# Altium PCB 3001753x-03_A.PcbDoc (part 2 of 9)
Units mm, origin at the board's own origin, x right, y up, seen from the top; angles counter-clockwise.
Board outline 210 x 130 mm, 8 copper layers (1-TOP, 2-GND, 3-INTOP, 4-PWR, 5-PWR, 6-INBOT, 7-GND, 8-BOTTOM), stack 1.646 mm thick; 676 components, 623 nets, 2861 pads, 2382 vias.
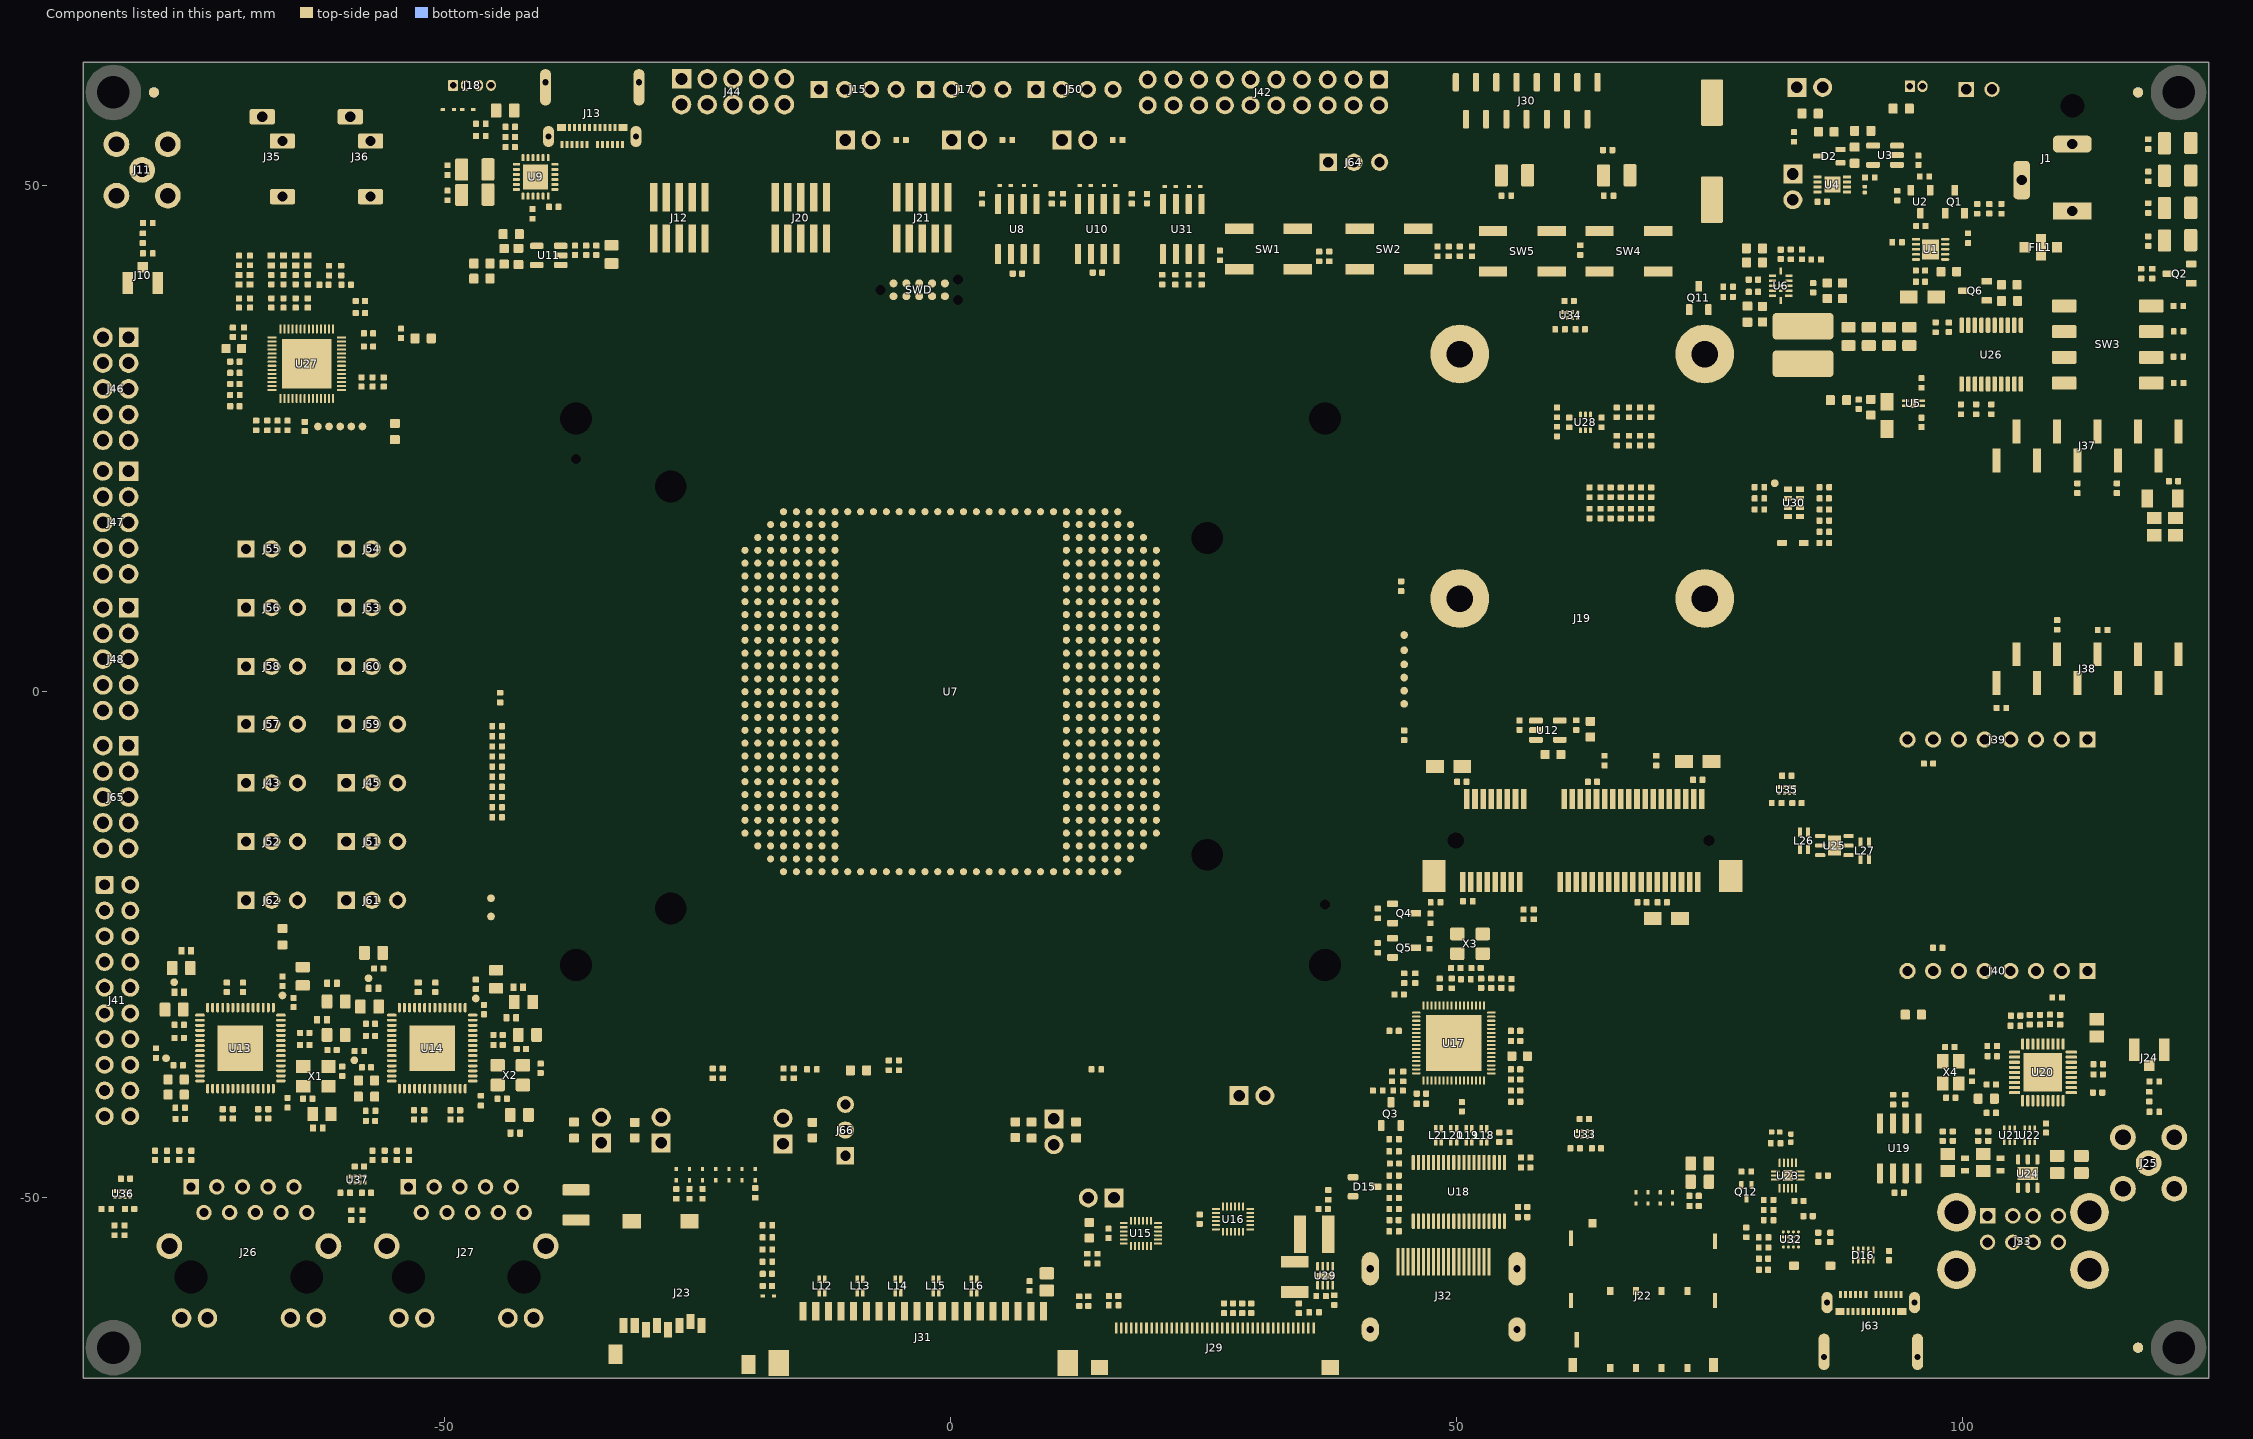
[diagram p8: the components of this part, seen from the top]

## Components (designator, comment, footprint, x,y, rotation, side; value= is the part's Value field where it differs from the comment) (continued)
U21 "ECMF02-2AMX6" QFN_6L_1.7mmX1.5mm_STM 104.6,-43.8 r270 top
U22 "ECMF02-2AMX6" QFN_6L_1.7mmX1.5mm_STM 106.6,-43.8 r270 top
U23 "PTN5110" QFN40P260X260X40-17T100X110N 82.7,-47.8 r270 top
U24 "TPD4E001DRSR" SON95P300X300X80-7N 106.4,-47.6 r90 top
U25 "TPD4E001DRSR" SON95P300X300X80-7N 87.3,-15.2 r0 top
U26 "SN74CB3Q3245PWR" SOP65P640X120-20N 102.8,33.3 r90 top
U27 "MAX98089" QFN40P700X700X80-57T560X560N -63.6,32.4 r90 top
U28 "DMN5L06VK-7" SOTFL50P160X60-6N 62.7,26.6 r90 top
U29 "LT3591" SON50P300X200X80-9T56X215N 37,-57.7 r270 top
U30 "RV-3028-C7" DFN_8P_RV3028C7 83.3,18.65 r0 top
U31 "LTC2862IS8-2#PBF" SOIC127P600X175-8N#1 22.9,45.7 r90 top
U32 "NX5P3290" BGA16N50P4X4_205X205X59B32N 83,-54.1 r90 top
U33 "NTS0102GT" PSON50P195X100X50-8N 62.643,-43.693 r270 top
U34 "NTS0102GT" PSON50P195X100X50-8N 61.2,37.2 r270 top
U35 "NTS0102GT" PSON50P195X100X50-8N 82.6,-9.7 r270 top
U36 "NTS0102GT" PSON50P195X100X50-8N -81.8,-49.6 r270 top
U37 "NTS0102GT" PSON50P195X100X50-8N -58.6,-48.2 r270 top
X1 "RH100-25.000-20-EXT-TR" OSC210P320X250X90-4N#1 -62.7,-38 r270 top
X2 "RH100-25.000-20-EXT-TR" OSC210P320X250X90-4N#2 -43.5,-37.875 r270 top
X3 "RH100-25.000-20-EXT-TR" OSC210P320X250X90-4N#2 51.305,-24.9 r270 top
X4 "24MHz" XTAL_C3E-3427 98.8,-37.6 r90 top

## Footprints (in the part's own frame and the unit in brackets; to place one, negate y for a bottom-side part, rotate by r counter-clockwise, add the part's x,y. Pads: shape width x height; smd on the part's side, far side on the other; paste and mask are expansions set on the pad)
BGA16N50P4X4_205X205X59B32N [mm] "Ball Grid Array (BGA), 0.50 mm pitch, square; 16 pin, 2.05 mm L X 2.05 mm W X 0.595 mm H body"
  round 0.3 smd mask+0.05: A1(-0.75,0.75) A2(-0.25,0.75) A3(0.25,0.75) A4(0.75,0.75) B1(-0.75,0.25) B2(-0.25,0.25) B3(0.25,0.25) B4(0.75,0.25) C1(-0.75,-0.25) C2(-0.25,-0.25) C3(0.25,-0.25) C4(0.75,-0.25) D1(-0.75,-0.75) D2(-0.25,-0.75) D3(0.25,-0.75) D4(0.75,-0.75)
  body extent -1.02,-1.02 1.02,1.02, height 0.6
"BOBBINTRON_SMA A700T" [mil] "SMA JACK RA"
  round 100 hole 55.12: 1(0,0)
  round 100 hole 61: 2(-100,100) 3(100,100) 4(-100,-100) 5(100,-100)
  body extent -137,-138 457,138, height 398
CAPC1005X55L [mm]
  rrect25% 0.52x0.52 smd mask+0.05: 1(-0.4,0) 2(0.4,0)
  body extent -0.5,-0.25 0.5,0.25, height 0.55
CAPC1005X55N#1 [mm]
  rrect30% 0.6x0.62 smd mask+0.05: 1(-0.46,0) 2(0.46,0)
  body extent -0.5,-0.25 0.5,0.25, height 0.55
CAPC1005X55N#2 [mm]
  rrect30% 0.6x0.62 smd mask+0.1: 1(-0.46,0) 2(0.46,0)
  body extent -0.5,-0.25 0.5,0.25, height 0.55
CAPC1608X90N [mm] "0603"
  rrect22% 0.89x0.93 smd: 1(-0.77,0) 2(0.77,0)
  body extent -0.8,-0.4 0.8,0.4, height 0.9
CAPC2013X135N#1 [mm] "0805, 1.35mm max height"
  rrect25% 1.05x1.4 smd: 1(-0.9,0) 2(0.9,0)
  body extent -1,-0.62 1,0.63, height 1.35
CAPC2013X135N#2 [mm] "0805, 1.35mm max height"
  rect 1.05x1.4 smd: 1(-0.9,0) 2(0.9,0)
  body extent -1,-0.62 1,0.63, height 1.35
CAPC3216X190N [mm]
  rect 1.15x1.8 smd: 1(-1.5,0) 2(1.5,0)
  body extent -1.6,-0.8 1.6,0.8, height 1.9
CAPC3225X250N [mm]
  rect 1.15x2.7 smd: 1(-1.5,0) 2(1.5,0)
  body extent -1.6,-1.26 1.6,1.26, height 2.52
CAPMP3216X120N [mm]
  rect 1.75x1.3 smd: 1(-1.35,0) 2(1.35,0)
  body extent -1.6,-0.8 1.6,0.8, height 1.6
CC93_DVK [mm]
  round 0.7 smd: A4(-20.32,-13.97) A5(-20.32,-12.7) A6(-20.32,-11.43) A7(-20.32,-10.16) A8(-20.32,-8.89) A9(-20.32,-7.62) A10(-20.32,-6.35) A11(-20.32,-5.08) A12(-20.32,-3.81) A13(-20.32,-2.54) A14(-20.32,-1.27) A15(-20.32,0) A16(-20.32,1.27) A17(-20.32,2.54) A18(-20.32,3.81) A19(-20.32,5.08) A20(-20.32,6.35) A21(-20.32,7.62) A22(-20.32,8.89) A23(-20.32,10.16) A24(-20.32,11.43) A25(-20.32,12.7) A26(-20.32,13.97) AA1(5.08,-17.78) AA29(5.08,17.78) AB1(6.35,-17.78) AB29(6.35,17.78) AC1(7.62,-17.78) AC29(7.62,17.78) AD1(8.89,-17.78) AD29(8.89,17.78) AE1(10.16,-17.78) AE29(10.16,17.78) AF1(11.43,-17.78) AF2(11.43,-16.51) AF3(11.43,-15.24) AF4(11.43,-13.97) AF5(11.43,-12.7) AF6(11.43,-11.43) AF7(11.43,-10.16) AF8(11.43,-8.89) AF9(11.43,-7.62) AF10(11.43,-6.35) AF11(11.43,-5.08) AF12(11.43,-3.81) AF13(11.43,-2.54) AF14(11.43,-1.27) AF15(11.43,0) AF16(11.43,1.27) AF17(11.43,2.54) AF18(11.43,3.81) AF19(11.43,5.08) AF20(11.43,6.35) AF21(11.43,7.62) AF22(11.43,8.89) AF23(11.43,10.16) AF24(11.43,11.43) AF25(11.43,12.7) AF26(11.43,13.97) AF27(11.43,15.24) AF28(11.43,16.51) AF29(11.43,17.78) AG1(12.7,-17.78) AG2(12.7,-16.51) AG3(12.7,-15.24) AG4(12.7,-13.97) AG5(12.7,-12.7) AG6(12.7,-11.43) AG7(12.7,-10.16) AG8(12.7,-8.89) AG9(12.7,-7.62) AG10(12.7,-6.35) AG11(12.7,-5.08) AG12(12.7,-3.81) AG13(12.7,-2.54) AG14(12.7,-1.27) AG15(12.7,0) AG16(12.7,1.27) AG17(12.7,2.54) AG18(12.7,3.81) AG19(12.7,5.08) AG20(12.7,6.35) AG21(12.7,7.62) AG22(12.7,8.89) AG23(12.7,10.16) AG24(12.7,11.43) AG25(12.7,12.7) AG26(12.7,13.97) AG27(12.7,15.24) AG28(12.7,16.51) AG29(12.7,17.78) AH1(13.97,-17.78) AH2(13.97,-16.51) AH3(13.97,-15.24) AH4(13.97,-13.97) AH5(13.97,-12.7) AH6(13.97,-11.43) AH7(13.97,-10.16) AH8(13.97,-8.89) AH9(13.97,-7.62) AH10(13.97,-6.35) AH11(13.97,-5.08) AH12(13.97,-3.81) AH13(13.97,-2.54) AH14(13.97,-1.27) AH15(13.97,0) AH16(13.97,1.27) AH17(13.97,2.54) AH18(13.97,3.81) AH19(13.97,5.08) AH20(13.97,6.35) AH21(13.97,7.62) AH22(13.97,8.89) AH23(13.97,10.16) AH24(13.97,11.43) AH25(13.97,12.7) AH26(13.97,13.97) AH27(13.97,15.24) AH28(13.97,16.51) AH29(13.97,17.78) AJ1(15.24,-17.78) AJ2(15.24,-16.51) AJ3(15.24,-15.24) AJ4(15.24,-13.97) AJ5(15.24,-12.7) AJ6(15.24,-11.43) AJ7(15.24,-10.16) AJ8(15.24,-8.89) AJ9(15.24,-7.62) AJ10(15.24,-6.35) AJ11(15.24,-5.08) AJ12(15.24,-3.81) AJ13(15.24,-2.54) AJ14(15.24,-1.27) AJ15(15.24,0) AJ16(15.24,1.27) AJ17(15.24,2.54) AJ18(15.24,3.81) AJ19(15.24,5.08) AJ20(15.24,6.35) AJ21(15.24,7.62) AJ22(15.24,8.89) AJ23(15.24,10.16) AJ24(15.24,11.43) AJ25(15.24,12.7) AJ26(15.24,13.97) AJ27(15.24,15.24) AJ28(15.24,16.51) AJ29(15.24,17.78) AK1(16.51,-17.78) AK2(16.51,-16.51) AK3(16.51,-15.24) AK4(16.51,-13.97) AK5(16.51,-12.7) AK6(16.51,-11.43) AK7(16.51,-10.16) AK8(16.51,-8.89) AK9(16.51,-7.62) AK10(16.51,-6.35) AK11(16.51,-5.08) AK12(16.51,-3.81) AK13(16.51,-2.54) AK14(16.51,-1.27) AK15(16.51,0) AK16(16.51,1.27) AK17(16.51,2.54) AK18(16.51,3.81) AK19(16.51,5.08) AK20(16.51,6.35) AK21(16.51,7.62) AK22(16.51,8.89) AK23(16.51,10.16) AK24(16.51,11.43) AK25(16.51,12.7) AK26(16.51,13.97) AK27(16.51,15.24) AK28(16.51,16.51) AK29(16.51,17.78) AL2(17.78,-16.51) AL3(17.78,-15.24) AL4(17.78,-13.97) AL5(17.78,-12.7) AL6(17.78,-11.43) AL7(17.78,-10.16) AL8(17.78,-8.89) AL9(17.78,-7.62) AL10(17.78,-6.35) AL11(17.78,-5.08) AL12(17.78,-3.81) AL13(17.78,-2.54) AL14(17.78,-1.27) AL15(17.78,0) AL16(17.78,1.27) AL17(17.78,2.54) AL18(17.78,3.81) AL19(17.78,5.08) AL20(17.78,6.35) AL21(17.78,7.62) AL22(17.78,8.89) AL23(17.78,10.16) AL24(17.78,11.43) AL25(17.78,12.7) AL26(17.78,13.97) AL27(17.78,15.24) AL28(17.78,16.51) AM3(19.05,-15.24) AM4(19.05,-13.97) AM5(19.05,-12.7) AM6(19.05,-11.43) AM7(19.05,-10.16) AM8(19.05,-8.89) AM9(19.05,-7.62) AM10(19.05,-6.35) AM11(19.05,-5.08) AM12(19.05,-3.81) AM13(19.05,-2.54) AM14(19.05,-1.27) AM15(19.05,0) AM16(19.05,1.27) AM17(19.05,2.54) AM18(19.05,3.81) AM19(19.05,5.08) AM20(19.05,6.35) AM21(19.05,7.62) AM22(19.05,8.89) AM23(19.05,10.16) AM24(19.05,11.43) AM25(19.05,12.7) AM26(19.05,13.97) AM27(19.05,15.24) AN4(20.32,-13.97) AN5(20.32,-12.7) AN6(20.32,-11.43) AN7(20.32,-10.16) AN8(20.32,-8.89) AN9(20.32,-7.62) AN10(20.32,-6.35) AN11(20.32,-5.08) AN12(20.32,-3.81) AN13(20.32,-2.54) AN14(20.32,-1.27) AN15(20.32,0) AN16(20.32,1.27) AN17(20.32,2.54) AN18(20.32,3.81) AN19(20.32,5.08) AN20(20.32,6.35) AN21(20.32,7.62) AN22(20.32,8.89) AN23(20.32,10.16) AN24(20.32,11.43) AN25(20.32,12.7) AN26(20.32,13.97) B3(-19.05,-15.24) B4(-19.05,-13.97) B5(-19.05,-12.7) B6(-19.05,-11.43) B7(-19.05,-10.16) B8(-19.05,-8.89) B9(-19.05,-7.62) B10(-19.05,-6.35) B11(-19.05,-5.08) B12(-19.05,-3.81) B13(-19.05,-2.54) B14(-19.05,-1.27) B15(-19.05,0) B16(-19.05,1.27) B17(-19.05,2.54) B18(-19.05,3.81) B19(-19.05,5.08) B20(-19.05,6.35) B21(-19.05,7.62) B22(-19.05,8.89) B23(-19.05,10.16) B24(-19.05,11.43) B25(-19.05,12.7) B26(-19.05,13.97) B27(-19.05,15.24) C2(-17.78,-16.51) C3(-17.78,-15.24) C4(-17.78,-13.97) C5(-17.78,-12.7) C6(-17.78,-11.43) C7(-17.78,-10.16) C8(-17.78,-8.89) C9(-17.78,-7.62) C10(-17.78,-6.35) C11(-17.78,-5.08) C12(-17.78,-3.81) C13(-17.78,-2.54) C14(-17.78,-1.27) C15(-17.78,0) C16(-17.78,1.27) C17(-17.78,2.54) C18(-17.78,3.81) C19(-17.78,5.08) C20(-17.78,6.35) C21(-17.78,7.62) C22(-17.78,8.89) C23(-17.78,10.16) C24(-17.78,11.43) C25(-17.78,12.7) C26(-17.78,13.97) C27(-17.78,15.24) C28(-17.78,16.51) D1(-16.51,-17.78) D2(-16.51,-16.51) D3(-16.51,-15.24) D4(-16.51,-13.97) D5(-16.51,-12.7) D6(-16.51,-11.43) D7(-16.51,-10.16) D8(-16.51,-8.89) D9(-16.51,-7.62) D10(-16.51,-6.35) D11(-16.51,-5.08) D12(-16.51,-3.81) D13(-16.51,-2.54) D14(-16.51,-1.27) D15(-16.51,0) D16(-16.51,1.27) D17(-16.51,2.54) D18(-16.51,3.81) D19(-16.51,5.08) D20(-16.51,6.35) D21(-16.51,7.62) D22(-16.51,8.89) D23(-16.51,10.16) D24(-16.51,11.43) D25(-16.51,12.7) D26(-16.51,13.97) D27(-16.51,15.24) D28(-16.51,16.51) D29(-16.51,17.78) E1(-15.24,-17.78) E2(-15.24,-16.51) E3(-15.24,-15.24) E4(-15.24,-13.97) E5(-15.24,-12.7) E6(-15.24,-11.43) E7(-15.24,-10.16) E8(-15.24,-8.89) E9(-15.24,-7.62) E10(-15.24,-6.35) E11(-15.24,-5.08) E12(-15.24,-3.81) E13(-15.24,-2.54) E14(-15.24,-1.27) E15(-15.24,0) E16(-15.24,1.27) E17(-15.24,2.54) E18(-15.24,3.81) E19(-15.24,5.08) E20(-15.24,6.35) E21(-15.24,7.62) E22(-15.24,8.89) E23(-15.24,10.16) E24(-15.24,11.43) E25(-15.24,12.7) E26(-15.24,13.97) E27(-15.24,15.24) E28(-15.24,16.51) E29(-15.24,17.78) F1(-13.97,-17.78) F2(-13.97,-16.51) F3(-13.97,-15.24) F4(-13.97,-13.97) F5(-13.97,-12.7) F6(-13.97,-11.43) F7(-13.97,-10.16) F8(-13.97,-8.89) F9(-13.97,-7.62) F10(-13.97,-6.35) F11(-13.97,-5.08) F12(-13.97,-3.81) F13(-13.97,-2.54) F14(-13.97,-1.27) F15(-13.97,0) F16(-13.97,1.27) F17(-13.97,2.54) F18(-13.97,3.81) F19(-13.97,5.08) F20(-13.97,6.35) F21(-13.97,7.62) F22(-13.97,8.89) F23(-13.97,10.16) F24(-13.97,11.43) F25(-13.97,12.7) F26(-13.97,13.97) F27(-13.97,15.24) F28(-13.97,16.51) F29(-13.97,17.78) G1(-12.7,-17.78) G2(-12.7,-16.51) G3(-12.7,-15.24) G4(-12.7,-13.97) G5(-12.7,-12.7) G6(-12.7,-11.43) G7(-12.7,-10.16) G8(-12.7,-8.89) G9(-12.7,-7.62) G10(-12.7,-6.35) G11(-12.7,-5.08) G12(-12.7,-3.81) G13(-12.7,-2.54) G14(-12.7,-1.27) G15(-12.7,0) G16(-12.7,1.27) G17(-12.7,2.54) G18(-12.7,3.81) G19(-12.7,5.08) G20(-12.7,6.35) G21(-12.7,7.62) G22(-12.7,8.89) G23(-12.7,10.16) G24(-12.7,11.43) G25(-12.7,12.7) G26(-12.7,13.97) G27(-12.7,15.24) G28(-12.7,16.51) G29(-12.7,17.78) H1(-11.43,-17.78) H2(-11.43,-16.51) H3(-11.43,-15.24) H4(-11.43,-13.97) H5(-11.43,-12.7) H6(-11.43,-11.43) H7(-11.43,-10.16) H8(-11.43,-8.89) H9(-11.43,-7.62) H10(-11.43,-6.35) H11(-11.43,-5.08) H12(-11.43,-3.81) H13(-11.43,-2.54) H14(-11.43,-1.27) H15(-11.43,0) H16(-11.43,1.27) H17(-11.43,2.54) H18(-11.43,3.81) H19(-11.43,5.08) H20(-11.43,6.35) H21(-11.43,7.62) H22(-11.43,8.89) H23(-11.43,10.16) H24(-11.43,11.43) H25(-11.43,12.7) H26(-11.43,13.97) H27(-11.43,15.24) H28(-11.43,16.51) H29(-11.43,17.78) J1(-10.16,-17.78) J29(-10.16,17.78) K1(-8.89,-17.78) K29(-8.89,17.78) L1(-7.62,-17.78) L29(-7.62,17.78) M1(-6.35,-17.78) M29(-6.35,17.78) N1(-5.08,-17.78) N29(-5.08,17.78) P1(-3.81,-17.78) P29(-3.81,17.78) R1(-2.54,-17.78) R29(-2.54,17.78) T1(-1.27,-17.78) T29(-1.27,17.78) U1(0,-17.78) U29(0,17.78) V1(1.27,-17.78) V29(1.27,17.78) W1(2.54,-17.78) W29(2.54,17.78) Y1(3.81,-17.78) Y29(3.81,17.78)
  round 0 hole 3.15: MH1(-37,27) MH2(37,27) MH3(37,-27) MH4(-37,-27)
  round 0 hole 1: MH5(-37,23) MH6(37,-21)
  Keep-Out Layer board cut-out: -10.75,16 -10.75,-16 -10.674,-16.383 -10.457,-16.707 -10.133,-16.924 -9.75,-17 -9.75,-17 10,-17 10.287,-16.943 10.53,-16.78 10.693,-16.537 10.75,-16.25 10.75,-16.25 10.75,16 10.616,16.5 10.25,16.866 9.75,17 9.75,17 -9.75,17 -10.133,16.924 -10.457,16.707 -10.674,16.383 -10.75,16
  Keep-Out Layer region: 36.3,-21 36.353,-20.732 36.505,-20.505 36.732,-20.353 37,-20.3 37,-20.3 37.268,-20.353 37.495,-20.505 37.647,-20.732 37.7,-21 37.7,-21 37.7,-21 37.647,-21.268 37.495,-21.495 37.268,-21.647 37,-21.7 37,-21.7 37,-21.7 36.732,-21.647 36.505,-21.495 36.353,-21.268 36.3,-21
  Keep-Out Layer region: -37.7,23 -37.647,23.268 -37.495,23.495 -37.268,23.647 -37,23.7 -37,23.7 -36.732,23.647 -36.505,23.495 -36.353,23.268 -36.3,23 -36.3,23 -36.3,23 -36.353,22.732 -36.505,22.505 -36.732,22.353 -37,22.3 -37,22.3 -37,22.3 -37.268,22.353 -37.495,22.505 -37.647,22.732 -37.7,23
  Keep-Out Layer region: -38.9,-27 -38.755,-26.273 -38.344,-25.656 -37.727,-25.245 -37,-25.1 -37,-25.1 -36.273,-25.245 -35.656,-25.656 -35.245,-26.273 -35.1,-27 -35.1,-27 -35.1,-27 -35.245,-27.727 -35.656,-28.344 -36.273,-28.755 -37,-28.9 -37,-28.9 -37,-28.9 -37.727,-28.755 -38.344,-28.344 -38.755,-27.727 -38.9,-27
  Keep-Out Layer region: 35.1,-27 35.245,-26.273 35.656,-25.656 36.273,-25.245 37,-25.1 37,-25.1 37.727,-25.245 38.344,-25.656 38.755,-26.273 38.9,-27 38.9,-27 38.9,-27 38.755,-27.727 38.344,-28.344 37.727,-28.755 37,-28.9 37,-28.9 37,-28.9 36.273,-28.755 35.656,-28.344 35.245,-27.727 35.1,-27
  Keep-Out Layer region: 35.1,27 35.245,27.727 35.656,28.344 36.273,28.755 37,28.9 37,28.9 37.727,28.755 38.344,28.344 38.755,27.727 38.9,27 38.9,27 38.9,27 38.755,26.273 38.344,25.656 37.727,25.245 37,25.1 37,25.1 37,25.1 36.273,25.245 35.656,25.656 35.245,26.273 35.1,27
  Keep-Out Layer region: -38.9,27 -38.755,27.727 -38.344,28.344 -37.727,28.755 -37,28.9 -37,28.9 -36.273,28.755 -35.656,28.344 -35.245,27.727 -35.1,27 -35.1,27 -35.1,27 -35.245,26.273 -35.656,25.656 -36.273,25.245 -37,25.1 -37,25.1 -37,25.1 -37.727,25.245 -38.344,25.656 -38.755,26.273 -38.9,27
  silkscreen extent -40,-30 40,30, body extent -22.5,-20 22.5,20, height 2.86
conn_CSCD443CCS011B00G [mil] "Bobbintron : CSCD443CCS011B00G"
  rect 65x150 hole 40 slot 126 at 90 deg: 1(0,0)
  rrect50% 65x150 / inner rect 65x150 / far side rrect50% 65x150 hole 40 slot 126 at 90 deg: 2(-260,0)
  rrect50% 150x65 / inner rect 150x65 / far side rrect50% 150x65 hole 40 slot 126 at 0 deg: 3(-120,-197.01)
  round 0 hole 93 unplated: 4(-409,0)
  body extent -571,-207 20,177, height 433
CUI_SJ1-3533N [mm] "CON PWR JCK STEREO 3.5MM R/A 3.05mm"
  rrect25% 1.5x2.5 hole 1 slot 2 at 90 deg: 1(-3.8,-0.1) 2(-1.4,1.9) 3(4.1,1.9)
  body extent -9,-4.1 9,4.1, height 12.3
DFN_8P_RV3028C7 [mm]
  rect 0.8x0.5 smd: 1(-0.6,1.35) 2(-0.6,0.45) 3(-0.6,-0.45) 4(-0.6,-1.35) 5(0.6,-1.35) 6(0.6,-0.45) 7(0.6,0.45) 8(0.6,1.35)
  body extent -0.75,-1.6 0.75,1.6, height 0.8
FCI_68002-102HLF#1 [mil]
  rect 74x74 hole 45: 1(0,0)
  round 74 hole 45: 2(100,0)
  body extent -51,-46 149,49, height 330
FCI_68002-102HLF#2 [mil]
  rect 74x74 hole 45: 1(-50,0)
  round 74 hole 45: 2(50,0)
  body extent -101,-46 99,49, height 330
FCI_SFW15S-2STE1LF [mm] "CONN FFC FPC VERT 15POS 1MM SMD"
  rrect50% 0.6x1.85 smd: 1(-7,-1.825) 2(-6,1.825) 3(-5,-1.825) 4(-4,1.825) 5(-3,-1.825) 6(-2,1.825) 7(-1,-1.825) 8(0,1.825) 9(1,-1.825) 10(2,1.825) 11(3,-1.825) 12(4,1.825) 13(5,-1.825) 14(6,1.825) 15(7,-1.825)
  silkscreen extent -9.16,-3.31 -7.64,-1.78, body extent -10.7,-2.25 10.7,2.25, height 5.31
fiducial_40mil_round [mil]
  round 40 smd paste-40 mask+20: 1(0,0)
  1-TOP pour cut-out: -40,0 -36.96,15.31 -28.28,28.28 -15.31,36.96 0,40 0,40 15.31,36.96 28.28,28.28 36.96,15.31 40,0 40,0 36.96,-15.31 28.28,-28.28 15.31,-36.96 0,-40 0,-40 -15.31,-36.96 -28.28,-28.28 -36.96,-15.31 -40,0
FIL_DLP11S [mm]
  rect 0.75x0.35 smd: 1(-0.65,-0.275) 2(0.65,-0.275) 3(0.65,0.275) 4(-0.65,0.275)
  body extent -0.67,-0.55 0.68,0.55, height 0.92
FIL_DLW21H [mm]
  rect 0.9x0.4 smd: 1(-0.85,-0.4) 2(0.85,-0.4) 3(0.85,0.4) 4(-0.85,0.4)
  1-TOP pour cut-out: -0.4,-0.85 -0.4,0.85 0.4,0.85 0.4,-0.85
  body extent -1.1,-0.7 1.1,0.7, height 1
FIL_NFE31P [mm]
  rect 1x1 smd: 1(-1.6,0) 3(1.6,0)
  rect 1x2.6 smd: 2(0,0)
  1-TOP keep-out region: 2.1,1.3 0.75,1.3 0.75,0.75 2.1,0.75
  1-TOP keep-out region: 2.1,-0.75 0.75,-0.75 0.75,-1.3 2.1,-1.3
  1-TOP keep-out region: -2.1,-1.3 -0.75,-1.3 -0.75,-0.75 -2.1,-0.75
  1-TOP keep-out region: -2.1,0.75 -0.75,0.75 -0.75,1.3 -2.1,1.3
  body extent -1.6,-0.8 1.6,0.8, height 1.6
FOXCONN_AS0B221-S68Q-7H [mm]
  round 5.8 hole 2.6: 0(-12.1,-23.9) 0(-12.1,-48.05) 0(12.1,-48.05) 0(12.1,-23.9)
  rect 0.55x2 smd: 1(11.8,4.1) 2(11.4,-4.1) 3(11,4.1) 4(10.6,-4.1) 5(10.2,4.1) 6(9.8,-4.1) 7(9.4,4.1) 8(9,-4.1) 9(8.6,4.1) 10(8.2,-4.1) 11(7.8,4.1) 12(7.4,-4.1) 13(7,4.1) 14(6.6,-4.1) 15(6.2,4.1) 16(5.8,-4.1) 17(2.2,4.1) 18(1.8,-4.1) 19(1.4,4.1) 20(1,-4.1) 21(0.6,4.1) 22(0.2,-4.1) 23(-0.2,4.1) 24(-0.6,-4.1) 25(-1,4.1) 26(-1.4,-4.1) 27(-1.8,4.1) 28(-2.2,-4.1) 29(-2.6,4.1) 30(-3,-4.1) 31(-3.4,4.1) 32(-3.8,-4.1) 33(-4.2,4.1) 34(-4.6,-4.1) 35(-5,4.1) 36(-5.4,-4.1) 37(-5.8,4.1) 38(-6.2,-4.1) 39(-6.6,4.1) 40(-7,-4.1) 41(-7.4,4.1) 42(-7.8,-4.1) 43(-8.2,4.1) 44(-8.6,-4.1) 45(-9,4.1) 46(-9.4,-4.1) 47(-9.8,4.1) 48(-10.2,-4.1) 49(-10.6,4.1) 50(-11,-4.1) 51(-11.4,4.1) 52(-11.8,-4.1)
  round 0 hole 1.6 unplated: H1(12.5,0)
  round 0 hole 1.1 unplated: H2(-12.5,0)
  rect 2.3x3.2 smd: MT1(14.65,3.5) MT2(-14.65,3.5)
  body extent -14.9,-4.75 14.9,4.75, height 6.8
HDMI21-S-RA-SMT-TR [mm]
  rect 0.3x2.7 smd: 1(-4.5,0) 2(-4,0) 3(-3.5,0) 4(-3,0) 5(-2.5,0) 6(-2,0) 7(-1.5,0) 8(-1,0) 9(-0.5,0) 10(0,0) 11(0.5,0) 12(1,0) 13(1.5,0) 14(2,0) 15(2.5,0) 16(3,0) 17(3.5,0) 18(4,0) 19(4.5,0)
  oval 1.7x3.3 hole 0.7 slot 2.3 at 90 deg: M1(-7.25,0.7) M2(7.25,0.7)
  oval 1.7x2.4 hole 0.7 slot 1.4 at 90 deg: M3(-7.25,6.7) M4(7.25,6.7)
HIROSE_DF14A-20P-1.25H [mm]
  rect 0.7x1.8 smd: 1(11.875,-2.55) 2(10.625,-2.55) 3(9.375,-2.55) 4(8.125,-2.55) 5(6.875,-2.55) 6(5.625,-2.55) 7(4.375,-2.55) 8(3.125,-2.55) 9(1.875,-2.55) 10(0.625,-2.55) 11(-0.625,-2.55) 12(-1.875,-2.55) 13(-3.125,-2.55) 14(-4.375,-2.55) 15(-5.625,-2.55) 16(-6.875,-2.55) 17(-8.125,-2.55) 18(-9.375,-2.55) 19(-10.625,-2.55) 20(-11.875,-2.55)
  rect 2x2.6 smd: MT1(14.275,2.55) MT21(-14.275,2.55)
  silkscreen extent 12.75,-3.05 13.25,-2.55, body extent -14.97,-3.02 14.97,3.67, height 2.49
HIROSE_U.FL-R-SMT(01) [mm]
  rect 1x1.05 smd: 1(0,-1.525)
  rect 1.05x2.2 smd: 2(-1.475,0.025) 3(1.475,0.025)
  1-TOP pour cut-out: -0.95,1.125 0.95,1.125 0.95,-1.075 -0.95,-1.075
  body extent -1.5,-1.5 1.5,1.6, height 1.25
IND_1610 [mm]
  rect 0.8x0.55 smd: A(0,-0.626) K(0,0.624)
  body extent -0.55,-0.85 0.55,0.85, height 0.62
IND_DG6045C [mm]
  rrect25% 2.6x6 smd mask+0.1: 1(-1.85,0) 2(1.85,0)
  1-TOP keep-out region: -0.4,-3.101 0.45,-3.101 0.45,3.099 -0.4,3.099
  body extent -3.15,-3.15 3.15,3.15, height 4.5
IND_NR4018T220M [mm]
  rect 1.2x3.7 smd: 1(-1.4,0) 2(1.4,0)
  body extent -2.1,-2.05 2.1,2.05, height 1.5
INDC1005X60N#1 [mm]
  rrect25% 0.59x0.72 smd: 1(-0.48,0) 2(0.48,0)
  body extent -0.5,-0.25 0.5,0.25, height 0.6
INDC1005X60N#2 [mm]
  rect 0.59x0.72 smd: 1(-0.48,0) 2(0.48,0)
  body extent -0.5,-0.25 0.5,0.25, height 0.6
INDC2013X110N#1 [mm]
  rrect25% 1.2x1.45 smd: 1(-0.85,0) 2(0.85,0)
  body extent -1,-0.62 1,0.63, height 1.1
INDC2013X110N#2 [mm]
  rect 1.2x1.45 smd: 1(-0.85,0) 2(0.85,0)
  body extent -1,-0.62 1,0.63, height 1.1
J8_THT_0.1_FEMALE [mm]
  rect 1.6x1.6 hole 1: 1(0,0)
  round 1.6 hole 1: 2(2.54,0) 3(5.08,0) 4(7.62,0) 5(10.16,0) 6(12.7,0) 7(15.24,0) 8(17.78,0)
  body extent -1.52,-1.27 19.3,1.27, height 8.51
KYCON_KUSBX-AS2N_Flex [mm]
  rect 1.524x1.524 hole 1: A1(0,0)
  round 1.524 hole 1: A2(2.5,0) A3(4.5,0) A4(7,0) B1(0,-2.62) B2(2.5,-2.62) B3(4.5,-2.62) B4(7,-2.62)
  round 3.81 hole 2.362: SH1(-3.07,-5.33) SH2(-3.07,0.35) SH3(10.07,-5.33) SH4(10.07,0.35)
  body extent -4.33,-16.08 11.33,1.42, height 16.1
LABEL_10x10 [mm]
LEDM3020X130N [mm]
  rrect25% 1.3x2.2 smd: A(-1.3,-0.025) K(1.3,0)
  body extent -1.5,-1 1.5,1, height 1.31
LEDM3020X130N_GREEN [mm]
  rrect25% 1.3x2.2 smd: A(-1.3,-0.025) K(1.3,0)
  body extent -1.5,-1 1.5,1, height 1.31
LEDM3020X130N_YELLOW [mm]
  rrect25% 1.3x2.2 smd: A(-1.3,-0.025) K(1.3,0)
  body extent -1.5,-1 1.5,1, height 1.31
MOLEX_53047-0210_Flex [mm]
  rrect20% 1x1.15 hole 0.65: 1(0,0)
  oval 1x1.15 hole 0.65: 2(1.25,0)
  silkscreen extent -2.51,-0.25 -2,0.25, body extent -1.52,-1.15 2.73,2.05, height 4.2
MOLEX_53047-0410 [mm]
  rrect20% 0.95x1.1 hole 0.65: 1(0,0)
  oval 0.95x1.1 hole 0.65: 2(1.25,0) 3(2.5,0) 4(3.75,0)
  silkscreen extent -2.63,-0.25 -2.12,0.25, body extent -1.52,-1.15 5.23,2.05, height 4.2
MOLEX_78727-0001 [mm]
  rect 0.8x0.6 smd: 1(7.62,4.38) 2(7.62,1.84) 3(7.62,-0.7) 4(7.62,-3.24) 5(0,4.38) 6(0,1.84) 7(0,-0.7) 8(0,-3.24)
  rect 0.85x0.8 smd: 9(-6.7,-4.98)
  rect 1.5x0.42 smd: 10(4.82,-6.54) 12(0.94,7.11) 13(-4.92,7.11) 14(-5.22,-7.11) 15(0.94,-7.11)
  rect 1.4x0.87 smd: 11(7.29,6.95) 16(7.29,-6.95)
  body extent -7.29,-7.26 7.93,7.27, height 1.4
MOLEX_87914-1016 [mil]
  rect 76x76 hole 47: 1(0,0)
  round 76 hole 47: 2(0,-100) 3(100,0) 4(100,-100) 5(200,0) 6(200,-100) 7(300,0) 8(300,-100) 9(400,0) 10(400,-100)
  silkscreen extent -90,-10 -70,10, body extent -50,-148 450,48, height 320
MOLEX_201267-0005 [mm]
  rect 0.3x0.7 smd mask+0.05: A1(-3,3.965) A2(-2.5,3.965) A3(-2,3.965) A4(-1.5,3.965) A5(-1,3.965) A6(-0.5,3.965) A7(0.5,3.965) A8(1,3.965) A9(1.5,3.965) A10(2,3.965) A11(2.5,3.965) A12(3,3.965) B2(2.25,2.265) B3(1.75,2.265) B4(1.25,2.265) B5(0.75,2.265) B6(0.25,2.265) B7(-0.25,2.265) B8(-0.75,2.265) B9(-1.25,2.265) B10(-1.75,2.265) B11(-2.25,2.265)
  rect 0.9x0.7 smd mask+0.05: B1(3.05,2.265) B12(-3.05,2.265)
  oval 1.1x2.1 hole 0.6 slot 1.6 at 90 deg mask+0.05: MT1(-4.32,3.155) MT2(4.32,3.155)
  oval 1.1x3.6 hole 0.6 slot 2.1 at 90 deg copper offset 0,0.5 mask+0.05: MT3(-4.62,-2.205) MT4(4.62,-2.205)
  body extent -4.69,-4.15 4.69,4.15, height 3.7
MOLEX_500873-0806 [mm]
  rect 0.8x1.5 smd: 1(0,0) 2(1.1,-0.4) 3(2.2,0) 4(3.3,0.425) 5(4.4,0) 6(5.5,0.425) 7(6.6,0) 8(7.7,0)
  rect 1.8x1.4 smd: 9(1.2,-10.3) 10(6.9,-10.3)
  rect 1.4x1.9 smd: 11(8.5,2.85) 12(-4.65,3.85)
  1-TOP region: 8.6,0.8 9.2,0.8 9.2,-11 8.6,-11
  body extent -5.05,-10.7 8.95,4.5, height 1.87
NEXC474Z3.5V10.5X8.5TRF [mm] "CAP_10.8mmx10.5mmx8.5mm_NEXC"
  rrect16% 2.2x4.6 smd: 1(0,4.8) 2(0,-4.8)
  silkscreen extent -3.92,5.65 -1.72,7.65, body extent -5.4,-6.1 5.4,6.1, height 8.5
OMRON_XF2M-4015-1A [mm]
  rect 0.25x1.1 smd: 1(-9.75,1.95) 2(-9.25,1.95) 3(-8.75,1.95) 4(-8.25,1.95) 5(-7.75,1.95) 6(-7.25,1.95) 7(-6.75,1.95) 8(-6.25,1.95) 9(-5.75,1.95) 10(-5.25,1.95) 11(-4.75,1.95) 12(-4.25,1.95) 13(-3.75,1.95) 14(-3.25,1.95) 15(-2.75,1.95) 16(-2.25,1.95) 17(-1.75,1.95) 18(-1.25,1.95) 19(-0.75,1.95) 20(-0.25,1.95) 21(0.25,1.95) 22(0.75,1.95) 23(1.25,1.95) 24(1.75,1.95) 25(2.25,1.95) 26(2.75,1.95) 27(3.25,1.95) 28(3.75,1.95) 29(4.25,1.95) 30(4.75,1.95) 31(5.25,1.95) 32(5.75,1.95) 33(6.25,1.95) 34(6.75,1.95) 35(7.25,1.95) 36(7.75,1.95) 37(8.25,1.95) 38(8.75,1.95) 39(9.25,1.95) 40(9.75,1.95)
  rect 1.7x1.5 smd: M1(11.4,-1.95) M2(-11.4,-1.95)
  silkscreen extent -10,2.9 -9.5,3.4, body extent -12.05,-2.9 12.05,3.3, height 2.18
OSC210P320X250X90-4N#1 [mm]
  rect 1.25x1.425 smd: 1(-0.975,1.25) 2(-0.975,-1.25) 3(0.975,-1.25) 4(0.975,1.25)
  body extent -1.3,-1.63 1.3,1.62, height 0.6
OSC210P320X250X90-4N#2 [mm]
  rrect25% 1.25x1.425 smd: 1(-0.975,1.25) 2(-0.975,-1.25) 3(0.975,-1.25) 4(0.975,1.25)
  body extent -1.3,-1.62 1.3,1.63, height 0.9
P4_STR_C2.54_H5.84 [mm]
  rect 1.7x1.7 hole 1: 1(0,0)
  round 1.7 hole 1: 2(0,-2.54) 3(0,-5.08) 4(0,-7.62)
  body extent -1.27,-8.89 1.27,1.4, height 8.39
PSON50P195X100X50-8N [mm] "Pullback Small Outline No-Lead (PSON), 0.50 mm pitch; 8 pin, 1.95 mm L X 1.00 mm W X 0.50 mm H body"
  rrect25% 0.4x0.3 smd mask+0.05: 1(-0.3,0.75) 2(-0.3,0.25) 3(-0.3,-0.25) 4(-0.3,-0.75) 5(0.3,-0.75) 6(0.3,-0.25) 7(0.3,0.25) 8(0.3,0.75)
  body extent -0.5,-0.97 0.5,0.97, height 0.5
QFN40P260X260X40-17T100X110N [mm] "Quad Flat No-Lead (QFN with Tab), 0.40 mm pitch; square, 5 pin X 3 pin, 2.60 mm L X 2.60 mm W X 0.40 mm H body"
  rrect25% 0.84x0.2 smd mask+0.05: 1(-1.25,0.8) 2(-1.25,0.4) 3(-1.25,0) 4(-1.25,-0.4) 5(-1.25,-0.8) 9(1.25,-0.8) 10(1.25,-0.4) 11(1.25,0) 12(1.25,0.4) 13(1.25,0.8)
  rrect25% 0.2x0.84 smd mask+0.05: 6(-0.4,-1.25) 7(0,-1.25) 8(0.4,-1.25) 14(0.4,1.25) 15(0,1.25) 16(-0.4,1.25)
  rrect25% 1.1x1 smd paste-0.153 mask+0.05: 17(0,0)
  body extent -1.35,-1.35 1.35,1.35, height 0.4
QFN40P340X250X50-24N [mm] "Quad Flat No-Lead (QFN), 0.40 mm pitch; rect., 6 pin X 6 pin, 3.40 mm L X 2.50 mm W X 0.50 mm H body"
  rrect30% 0.765x0.2 smd mask+0.05: 1(-1.245,1) 2(-1.245,0.6) 3(-1.245,0.2) 4(-1.245,-0.2) 5(-1.245,-0.6) 6(-1.245,-1) 13(1.245,-1) 14(1.245,-0.6) 15(1.245,-0.2) 16(1.245,0.2) 17(1.245,0.6) 18(1.245,1)
  rrect30% 0.2x0.765 smd mask+0.05: 7(-1,-1.695) 8(-0.6,-1.695) 9(-0.2,-1.695) 10(0.2,-1.695) 11(0.6,-1.695) 12(1,-1.695) 19(1,1.695) 20(0.6,1.695) 21(0.2,1.695) 22(-0.2,1.695) 23(-0.6,1.695) 24(-1,1.695)
  body extent -1.3,-1.75 1.3,1.75, height 0.5
QFN40P700X700X80-57T560X560N [mm] "Quad Flat No-Lead (QFN with Tab), 0.40 mm pitch; square, 14 pin X 14 pin, 7.00 mm L X 7.00 mm W X 0.80 mm H body"
  rrect50% 0.86x0.2 smd mask+0.05: 1(-3.43,2.6) 2(-3.43,2.2) 3(-3.43,1.8) 4(-3.43,1.4) 5(-3.43,1) 6(-3.43,0.6) 7(-3.43,0.2) 8(-3.43,-0.2) 9(-3.43,-0.6) 10(-3.43,-1) 11(-3.43,-1.4) 12(-3.43,-1.8) 13(-3.43,-2.2) 14(-3.43,-2.6) 29(3.43,-2.6) 30(3.43,-2.2) 31(3.43,-1.8) 32(3.43,-1.4) 33(3.43,-1) 34(3.43,-0.6) 35(3.43,-0.2) 36(3.43,0.2) 37(3.43,0.6) 38(3.43,1) 39(3.43,1.4) 40(3.43,1.8) 41(3.43,2.2) 42(3.43,2.6)
  rrect50% 0.2x0.86 smd mask+0.05: 15(-2.6,-3.43) 16(-2.2,-3.43) 17(-1.8,-3.43) 18(-1.4,-3.43) 19(-1,-3.43) 20(-0.6,-3.43) 21(-0.2,-3.43) 22(0.2,-3.43) 23(0.6,-3.43) 24(1,-3.43) 25(1.4,-3.43) 26(1.8,-3.43) 27(2.2,-3.43) 28(2.6,-3.43) 43(2.6,3.43) 44(2.2,3.43) 45(1.8,3.43) 46(1.4,3.43) 47(1,3.43) 48(0.6,3.43) 49(0.2,3.43) 50(-0.2,3.43) 51(-0.6,3.43) 52(-1,3.43) 53(-1.4,3.43) 54(-1.8,3.43) 55(-2.2,3.43) 56(-2.6,3.43)
  rect 4.9x4.9 smd paste-4.9 mask+0: 57(0,0)
  1-TOP region: -2.8,-2.8 -2.8,2.45 -2.45,2.8 2.8,2.8 2.8,-2.8 -2.8,-2.8
  body extent -3.55,-3.55 3.55,3.55, height 0.8
QFN40P750X750X80-65T620N [mm] "Quad Flat No-Lead (QFN with Tab), 0.40 mm pitch; square, 16 pin X 16 pin, 7.50 mm L X 7.50 mm W X 0.80 mm H body"
  rrect50% 0.81x0.2 smd mask+0.05: 1(-3.705,3) 2(-3.705,2.6) 3(-3.705,2.2) 4(-3.705,1.8) 5(-3.705,1.4) 6(-3.705,1) 7(-3.705,0.6) 8(-3.705,0.2) 9(-3.705,-0.2) 10(-3.705,-0.6) 11(-3.705,-1) 12(-3.705,-1.4) 13(-3.705,-1.8) 14(-3.705,-2.2) 15(-3.705,-2.6) 16(-3.705,-3) 33(3.705,-3) 34(3.705,-2.6) 35(3.705,-2.2) 36(3.705,-1.8) 37(3.705,-1.4) 38(3.705,-1) 39(3.705,-0.6) 40(3.705,-0.2) 41(3.705,0.2) 42(3.705,0.6) 43(3.705,1) 44(3.705,1.4) 45(3.705,1.8) 46(3.705,2.2) 47(3.705,2.6) 48(3.705,3)
  rrect50% 0.2x0.81 smd mask+0.05: 17(-3,-3.705) 18(-2.6,-3.705) 19(-2.2,-3.705) 20(-1.8,-3.705) 21(-1.4,-3.705) 22(-1,-3.705) 23(-0.6,-3.705) 24(-0.2,-3.705) 25(0.2,-3.705) 26(0.6,-3.705) 27(1,-3.705) 28(1.4,-3.705) 29(1.8,-3.705) 30(2.2,-3.705) 31(2.6,-3.705) 32(3,-3.705) 49(3,3.705) 50(2.6,3.705) 51(2.2,3.705) 52(1.8,3.705) 53(1.4,3.705) 54(1,3.705) 55(0.6,3.705) 56(0.2,3.705) 57(-0.2,3.705) 58(-0.6,3.705) 59(-1,3.705) 60(-1.4,3.705) 61(-1.8,3.705) 62(-2.2,3.705) 63(-2.6,3.705) 64(-3,3.705)
  rect 5.5x5.5 smd paste-5.5 mask+0: 65(0,0)
  1-TOP region: -3.1,-3.1 -3.1,2.75 -2.75,3.1 3.1,3.1 3.1,-3.1 -3.1,-3.1
  body extent -3.8,-3.8 3.8,3.8, height 0.8
QFN50P400X400X100-25 [mm]
  rrect50% 0.69x0.28 smd: 1(-1.9,1.25) 2(-1.9,0.75) 3(-1.9,0.25) 4(-1.9,-0.25) 5(-1.9,-0.75) 6(-1.9,-1.25) 13(1.9,-1.25) 14(1.9,-0.75) 15(1.9,-0.25) 16(1.9,0.25) 17(1.9,0.75) 18(1.9,1.25)
  rrect50% 0.28x0.69 smd: 7(-1.25,-1.9) 8(-0.75,-1.9) 9(-0.25,-1.9) 10(0.25,-1.9) 11(0.75,-1.9) 12(1.25,-1.9) 19(1.25,1.9) 20(0.75,1.9) 21(0.25,1.9) 22(-0.25,1.9) 23(-0.75,1.9) 24(-1.25,1.9)
  rect 2.5x2.5 smd: 25(0,0)
  body extent -2.07,-2.07 2.07,2.07, height 1.01
QFN50P600X600X100-37AN [mm]
  rrect50% 1.1x0.3 smd mask+0.05: 1(-2.8,2) 2(-2.8,1.5) 3(-2.8,1) 4(-2.8,0.5) 5(-2.8,0) 6(-2.8,-0.5) 7(-2.8,-1) 8(-2.8,-1.5) 9(-2.8,-2) 19(2.8,-2) 20(2.8,-1.5) 21(2.8,-1) 22(2.8,-0.5) 23(2.8,0) 24(2.8,0.5) 25(2.8,1) 26(2.8,1.5) 27(2.8,2)
  rrect50% 0.3x1.1 smd mask+0.05: 10(-2,-2.8) 11(-1.5,-2.8) 12(-1,-2.8) 13(-0.5,-2.8) 14(0,-2.8) 15(0.5,-2.8) 16(1,-2.8) 17(1.5,-2.8) 18(2,-2.8) 28(2,2.8) 29(1.5,2.8) 30(1,2.8) 31(0.5,2.8) 32(0,2.8) 33(-0.5,2.8) 34(-1,2.8) 35(-1.5,2.8) 36(-2,2.8)
  rect 3.8x3.8 smd: 37(0,0)
  body extent -3.05,-3.05 3.05,3.05, height 1.01
QFN56P8mmx8mm-4.50mmPAD [mm]
  oval 0.95x0.29 smd: 1(-4,3.25) 2(-4,2.75) 3(-4,2.25) 4(-4,1.75) 5(-4,1.25) 6(-4,0.75) 7(-4,0.25) 8(-4,-0.25) 9(-4,-0.75) 10(-4,-1.25) 11(-4,-1.75) 12(-4,-2.25) 13(-4,-2.75) 14(-4,-3.25) 29(4,-3.25) 30(4,-2.75) 31(4,-2.25) 32(4,-1.75) 33(4,-1.25) 34(4,-0.75) 35(4,-0.25) 36(4,0.25) 37(4,0.75) 38(4,1.25) 39(4,1.75) 40(4,2.25) 41(4,2.75) 42(4,3.25)
  oval 0.29x0.95 smd: 15(-3.25,-4) 16(-2.75,-4) 17(-2.25,-4) 18(-1.75,-4) 19(-1.25,-4) 20(-0.75,-4) 21(-0.25,-4) 22(0.25,-4) 23(0.75,-4) 24(1.25,-4) 25(1.75,-4) 26(2.25,-4) 27(2.75,-4) 28(3.25,-4) 43(3.25,4) 44(2.75,4) 45(2.25,4) 46(1.75,4) 47(1.25,4) 48(0.75,4) 49(0.25,4) 50(-0.25,4) 51(-0.75,4) 52(-1.25,4) 53(-1.75,4) 54(-2.25,4) 55(-2.75,4) 56(-3.25,4)
  rect 4.5x4.5 smd: 57(0,0)
  body extent -4.05,-4.06 4.05,4.04, height 0.91
QFN_6L_1.7mmX1.5mm_STM [mm]
  rect 0.6x0.25 smd paste+0 mask+0: 1(-0.65,0.5) 2(-0.65,0) 3(-0.65,-0.5) 4(0.65,-0.5) 5(0.65,0) 6(0.65,0.5)
  body extent -0.77,-0.88 0.77,0.88, height 0.56
QFN_MPS_MP2316 [mm]
  rect 0.75x0.25 smd mask+0.05: 1(-0.8,1)
  rect 0.7x0.25 smd mask+0.05: 2(-0.8,0.5) 3(-0.8,0) 4(-0.8,-0.5) 5(-0.8,-1) 7(0.8,-1) 8(0.8,-0.5) 9(0.8,0) 10(0.8,0.5) 11(0.8,1)
  rect 0.25x0.7 smd mask+0.05: 6(0,-1.45) 12(0,1.45)
  rect 0.35x0.25 smd mask+0.05: 13(0,0.5) 14(0,0)
  body extent -1,-1.5 1,1.5, height 1.01
RESC0603X28N [mm]
  rrect25% 0.37x0.4 smd mask+0.102: 1(-0.285,0) 2(0.285,0)
  body extent -0.3,-0.15 0.3,0.15, height 0.28
RESC1005X40N [mm]
  rrect25% 0.57x0.62 smd mask+0.05: 1(-0.48,0) 2(0.48,0)
  body extent -0.5,-0.25 0.5,0.25, height 0.4
RESC1609X55N#1 [mm]
  rrect30% 0.9x1 smd mask+0.05: 1(-0.8,0) 2(0.8,0)
  body extent -0.8,-0.4 0.8,0.4, height 0.55
RESC1609X55N#2 [mm]
  rrect22% 0.89x0.93 smd: 1(-0.77,0) 2(0.77,0)
  body extent -0.87,-0.48 0.87,0.48, height 0.55
RESC3225X60N [mm]
  rrect25% 1.1x2.7 smd: 1(-1.5,0) 2(1.5,0)
  body extent -1.6,-1.25 1.6,1.25, height 0.55
SAMTEC_FTSH-105-01-F-DV [mil]
  rect 110x29 smd: 1(-80,100) 2(80,100) 3(-80,50) 4(80,50) 5(-80,0) 6(80,0) 7(-80,-50) 8(80,-50) 9(-80,-100) 10(80,-100)
  silkscreen extent -175,90 -155,110, body extent -115,-208 115,208, height 325
Samtec_SMM-110-02-F-S [mm]
  rect 0.8x2.35 smd: 1(-9,-1.425) 2(-7,1.425) 3(-5,-1.425) 4(-3,1.425) 5(-1,-1.425) 6(1,1.425) 7(3,-1.425) 8(5,1.425) 9(7,-1.425) 10(9,1.425)
  silkscreen extent -10.18,-1.74 -9.85,-1.41, body extent -9.99,-2.16 10,2.16, height 4.83
SAMTEC_TSW-103-07-G-S [mm]
  rect 1.7x1.7 hole 1: 1(0,2.54)
  round 1.7 hole 1: 2(0,0) 3(0,-2.54)
  body extent -1.27,-3.81 1.27,3.94, height 8.39
SAMTEC_TSW-110-26-L-D [mil] "150.08"
  rrect20% 70x70 hole 42: 1(-450,-50)
  round 70 hole 42: 2(-450,50) 3(-350,-50) 4(-350,50) 5(-250,-50) 6(-250,50) 7(-150,-50) 8(-150,50) 9(-50,-50) 10(-50,50) 11(50,-50) 12(50,50) 13(150,-50) 14(150,50) 15(250,-50) 16(250,50) 17(350,-50) 18(350,50) 19(450,-50) 20(450,50)
  body extent -500,-100 500,100, height 330
SOD3716X135N [mm]
  rrect25% 1x0.8 smd: A(1.8,0) K(-1.8,0)
  body extent -1.85,-0.8 1.85,0.8, height 1.27
SODFL1006X43AN12 [mm]
  rrect25% 0.43x0.32 smd: 1(-0.55,0) 2(0.55,0)
  body extent -0.5,-0.3 0.5,0.3, height 0.4
SODFL2513X80N [mm]
  rrect25% 0.97x0.57 smd: A(1.07,0)
  rrect25% 0.97x0.6 smd: K(-1.07,0)
  body extent -1.25,-0.63 1.25,0.63, height 0.8
SOIC127P600X175-8N#1 [mm]
  rrect25% 1.97x0.6 smd mask+0.05: 1(-2.47,1.915) 2(-2.47,0.645) 3(-2.47,-0.625) 4(-2.47,-1.895) 5(2.47,-1.895) 6(2.47,-0.625) 7(2.47,0.645) 8(2.47,1.915)
  body extent -3.1,-2.48 3.1,2.52, height 1.75
SOIC127P600X175-8N#2 [mm]
  rect 1.97x0.6 smd mask+0.05: 1(-2.47,1.915) 2(-2.47,0.645) 3(-2.47,-0.625) 4(-2.47,-1.895) 5(2.47,-1.895) 6(2.47,-0.625) 7(2.47,0.645) 8(2.47,1.915)
  body extent -3.1,-2.48 3.1,2.52, height 1.75
SOIC254P991X420-8N [mm]
  rrect25% 2.44x1.3 smd mask+0.05: 1(-4.3,3.81) 2(-4.3,1.27) 3(-4.3,-1.27) 4(-4.3,-3.81) 5(4.3,-3.81) 6(4.3,-1.27) 7(4.3,1.27) 8(4.3,3.81)
  body extent -3.35,-5.75 3.5,5.75, height 4.2
SON50P120X160X60-5T55X91N [mm] "Small Outline No-Lead (SON with Tab), 0.50 mm pitch; 4 pin, 1.20 mm L X 1.60 mm W X 0.60 mm H body"
  rrect52% 0.67x0.27 smd mask+0.051: 1(-0.81,0.25) 2(-0.81,-0.25) 3(0.81,-0.25) 4(0.81,0.25)
  rect 0.55x0.91 smd paste-0.099 mask+0.025: 5(0,0)
  body extent -0.85,-0.6 0.85,0.6, height 0.6
SON50P250X100X50-10N [mm] "Small Outline No-Lead (SON), 0.50 mm pitch; 10 pin, 2.50 mm L X 1.00 mm W X 0.50 mm H body"
  rrect55% 0.7x0.22 smd mask+0.05: 1(-0.505,1) 2(-0.5,0.5) 3(-0.5,0) 4(-0.5,-0.5) 5(-0.5,-1) 6(0.5,-1) 7(0.5,-0.5) 8(0.5,0) 9(0.5,0.5) 10(0.5,1)
  body extent -0.55,-1.25 0.55,1.25, height 0.5
SON50P300X200X80-9N [mm]
  rect 0.3x0.8 smd: 1(-0.75,-1.45) 2(-0.25,-1.45) 3(0.25,-1.45) 4(0.75,-1.45) 5(0.75,1.45) 6(0.25,1.45) 7(-0.25,1.45) 8(-0.75,1.45)
  rect 1.6x1.6 smd: 9(0,0)
  body extent -1.05,-1.55 1.05,1.55, height 0.8
SON50P300X200X80-9T56X215N [mm] "Small Outline No-Lead (SON with Tab), 0.50 mm pitch; 8 pin, 3.00 mm L X 2.00 mm W X 0.80 mm H body"
  rrect52% 0.86x0.27 smd mask+0.025: 1(-0.935,0.75) 2(-0.935,0.25) 3(-0.935,-0.25) 4(-0.935,-0.75) 5(0.935,-0.75) 6(0.935,-0.25) 7(0.935,0.25) 8(0.935,0.75)
  rect 0.56x1.75 smd paste-1.75 mask+0: 9(0,0)
  1-TOP region: -0.28,-1.075 -0.28,0.875 -0.08,1.075 0.28,1.075 0.28,-1.075 -0.28,-1.075
  body extent -1.05,-1.5 1.05,1.5, height 0.8
SON50P300X300X80-11T164X238N [mm] "Small Outline No-Lead (SON with Tab), 0.50 mm pitch; 10 pin, 3.00 mm L X 3.00 mm W X 0.80 mm H body"
  rrect100% 0.83x0.26 smd mask+0.065: 1(-1.44,1) 2(-1.44,0.5) 3(-1.44,0) 4(-1.44,-0.5) 5(-1.44,-1) 6(1.44,-1) 7(1.44,-0.5) 8(1.44,0) 9(1.44,0.5) 10(1.44,1)
  rect 1.646x1.984 smd paste-1.984 mask+0: 11(0,0)
  body extent -1.55,-1.5 1.55,1.5, height 0.8
SON95P300X300X80-7N [mm]
  rrect50% 1x0.4 smd: 1(-1.4,0.95) 2(-1.4,0) 3(-1.4,-0.95) 4(1.4,-0.95) 5(1.4,0) 6(1.4,0.95)
  rect 1.3x2 smd: 7(0,0)
  body extent -1.58,-1.58 1.58,1.58, height 0.8
SOP50P640X120-38N [mm]
  rrect50% 1.5x0.3 smd: 1(-2.9,4.5) 2(-2.9,4) 3(-2.9,3.5) 4(-2.9,3) 5(-2.9,2.5) 6(-2.9,2) 7(-2.9,1.5) 8(-2.9,1) 9(-2.9,0.5) 10(-2.9,0) 11(-2.9,-0.5) 12(-2.9,-1) 13(-2.9,-1.5) 14(-2.9,-2) 15(-2.9,-2.5) 16(-2.9,-3) 17(-2.9,-3.5) 18(-2.9,-4) 19(-2.9,-4.5) 20(2.9,-4.5) 21(2.9,-4) 22(2.9,-3.5) 23(2.9,-3) 24(2.9,-2.5) 25(2.9,-2) 26(2.9,-1.5) 27(2.9,-1) 28(2.9,-0.5) 29(2.9,0) 30(2.9,0.5) 31(2.9,1) 32(2.9,1.5) 33(2.9,2) 34(2.9,2.5) 35(2.9,3) 36(2.9,3.5) 37(2.9,4) 38(2.9,4.5)
  body extent -3.2,-4.85 3.2,4.85, height 0.52
SOP65P640X120-20N [mm]
  rrect50% 1.5x0.45 smd mask+0.05: 1(-2.9,2.925) 2(-2.9,2.275) 3(-2.9,1.625) 4(-2.9,0.975) 5(-2.9,0.325) 6(-2.9,-0.325) 7(-2.9,-0.975) 8(-2.9,-1.625) 9(-2.9,-2.275) 10(-2.9,-2.925) 11(2.9,-2.925) 12(2.9,-2.275) 13(2.9,-1.625) 14(2.9,-0.975) 15(2.9,-0.325) 16(2.9,0.325) 17(2.9,0.975) 18(2.9,1.625) 19(2.9,2.275) 20(2.9,2.925)
  body extent -3.2,-3.25 3.2,3.25, height 1.2
SOT65P210X100-3AN [mm]
  rrect25% 1x0.5 smd: 1(-1.1,0.65) 2(-1.1,-0.65) 3(1.1,0)
  body extent -1.12,-1.1 1.12,1.1, height 1.1
SOT95P240X110_AXK-3N [mm]
  rrect50% 1.05x0.65 smd: A(-1.15,0.95) K(1.15,0) X(-1.15,-0.95)
  body extent -1.2,-1.46 1.2,1.46, height 1.1
SOT95P240X110_GSD-3N#1 [mm]
  rect 0.65x1.05 smd: D(0,1.15) G(-0.95,-1.15) S(0.95,-1.15)
  body extent -1.46,-1.2 1.46,1.2, height 1.1
SOT95P240X110_GSD-3N#2 [mm]
  rrect25% 1.05x0.65 smd: D(1.15,0) G(-1.15,0.95) S(-1.15,-0.95)
  body extent -1.2,-1.46 1.2,1.46, height 1.1
SOT95P280X145-5N [mm]
  rrect50% 1.36x0.6 smd: 1(-1.18,0.95) 2(-1.18,0) 3(-1.18,-0.95) 4(1.18,-0.95) 5(1.18,0.95)
  body extent -1.4,-1.45 1.4,1.45, height 1.45
SOTFL50P160X60-6N [mm]
  rrect53% 0.56x0.3 smd mask+0.05: 1(-0.78,0.5) 2(-0.78,0) 3(-0.78,-0.5) 4(0.78,-0.5) 5(0.78,0) 6(0.78,0.5)
  body extent -0.8,-0.8 0.8,0.8, height 0.6
SOTFL50P160X80_GSD-3N [mm]
  rrect25% 0.77x0.4 smd: D(0.69,0) G(-0.69,0.5) S(-0.69,-0.5)
  body extent -0.48,-0.85 0.48,0.85, height 0.8
SW_KSC221J [mm]
  rect 1x2.8 smd: 1(2,2.9) 2(2,-2.9) 3(-2,2.9) 4(-2,-2.9)
  body extent -3.1,-3.4 3.1,3.4, height 3.5
TC_TC2050-IDC-NL [mil]
  round 31 smd paste-50: 1(-100,-25) 2(-50,-25) 3(0,-25) 4(50,-25) 5(100,-25) 6(100,25) 7(50,25) 8(0,25) 9(-50,25) 10(-100,25)
  round 0 hole 39 unplated mask+4: MT1(-150,0) MT2(150,40) MT3(150,-40)
TE_640456-2 [mm] "CONN HEADER VERT 2POS .100 TIN"
  rect 1.5x1.5 hole 1.02: 1(-1.27,0)
  round 1.5 hole 1.02: 2(1.27,0)
  silkscreen extent -3.35,-0.25 -2.95,0.15, body extent -2.54,-3.14 2.54,2.7, height 10.03
TP0762 [mil] "30mil SMT Round Testpoint"
  round 30 smd paste-100: 1(0,0)
XMULTIPLE_XMG-J1B211 [mil]
  rect 60x60 hole 35 mask+4: 1(0,0)
  round 60 hole 35 mask+4: 2(50,-100) 3(100,0) 4(150,-100) 5(200,0) 6(250,-100) 7(300,0) 8(350,-100) 9(400,0) 10(450,-100)
  round 76 hole 47 mask+4: D1(-36.61,-510) D2(63.78,-510) D3(386.61,-510) D4(487.01,-510)
  round 0 hole 127.95 unplated mask+4: MNT1(0,-350) MNT2(450,-350)
  round 100 hole 63 mask+4: SHLD1(-84.25,-230) SHLD2(534.25,-230)
  body extent -169,-773 619,67, height 612
XTAL_C3E-3427 [mm]
  rect 1.4x1.15 smd: 1(-1.1,-0.8) 2(1.1,-0.8) 3(1.1,0.8) 4(-1.1,0.8)
  body extent -1.7,-1.35 1.7,1.35, height 0.75

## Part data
C1 C13 C14 C21: library part 1000998, "CAP CER 22UF 10V 20% X5R 0603", Manufacturer=Samsung, Manufacturer_Alt_1="TDK Corporation", Manufacturer_Alt_1_Part_Number=C1608X5R1A226M080AC, Manufacturer_Part_Number=CL10A226MP8NUNE, Package_Type=0603, Temp_Coef=X5R, Tolerance=20, Voltage=10V
C2 C16 C40 C41 C42: library part 1001196, "CAP TANT 100UF 6.3V 20% 1206", Manufacturer=Rohm, Manufacturer_Part_Number=TCTAL0J107M8R, Package_Type=3216, Tolerance=20%, Voltage=6.3V
C3 C12 C48 C111 C120 C125 C127 C129 C131 C133 C135 C140 C141 C147 C148 C175 C182 C197 C199: library part 1001168, "CAP CER 10UF 10V 20% X5R 0402", Manufacturer=Samsung, Manufacturer_Part_Number=CL05A106MP5NUNC, Package_Type=0402, Temp_Coef=X5R, Tolerance=20%, Voltage=10V
C4 C8 C10 C39 C139 C144 C158 C159 C160 C162 C163 C167 C169 C172 C174 C176 C177 C178 C179 C181 C183 C184 C189: library part 1001167, "CAP CER 1UF 10V 10% X5R 0402", Manufacturer=Murata, Manufacturer_Part_Number=GRM155R61A105KE15D, Package_Type=0402, Temp_Coef=X5R, Tolerance=10%, Voltage=10V
C5 C23: library part 1000007, "CAP 47pF 50V 5% NP0 0402", Manufacturer=Murata, Manufacturer_Alt_1="AVX Corporation", Manufacturer_Alt_1_Part_Number=04025A470JAT2A, Manufacturer_Part_Number=GRM1555C1H470JA01D, Package_Type=0402, Temp_Coef="C0G, NP0"
C6 C11 C15 C22 C27 C28 C29 C30 C32 C36 C37 C43 C44 C45 C46 C47 C49 C52 C53 C54 C55 C56 C57 C58 C60 C61 C63 C64 C65 C69 C72 C73 C74 C75 C77 C78 C81 C82 C83 C84 C85 C87 C88 C90 C91 C92 C96 C99 C100 C101 C102 C104 C105 C108 C109 C110 C112 C113 C115 C118 C119 C121 C122 C123 C124 C126 C128 C130 C132 C134 C136 C142 C143 C145 C146 C149 C150 C151 C152 C153 C154 C155 C157 C171 C173 C186 C187 C188 C191 C192 C193 C194 C198 C200 C201 C202 C203 C204 C205 C206 C207 C208 C209 C210 C211: library part 1000006, "CAP 100nF 16V 10% X7R 0402", Manufacturer=Murata, Manufacturer_Part_Number=GRM155R71C104KA88D, Package_Type=0402, Tolerance=10
C7 C24 C33 C38 C156 C180: library part 1001303, "CAP CER 2.2UF 16V 10% X5R 0603", Manufacturer="TDK Corporation", Manufacturer_Part_Number=C1608X5R1C225K080AB, Package_Type=0603, Tolerance=10%, Voltage=16V
C9: library part 1002775, "SMCAP, 0.47F 3.5V SUPERCAP 8.5x10.5x10.8mm SMT", Manufacturer=NIC
C17 C18 C19 C20 C26 C35 C50 C51 C59 C62 C66 C70 C76 C79 C86 C89 C93 C97 C103 C106: library part 1000111, "CAP CER 10UF 16V 10% X5R 0805", Manufacturer=Murata, Manufacturer_Part_Number=GRM21BR61C106KE15L, Package_Type=0805, Temp_Coef=X5R, Tolerance=10, Voltage=16V
C25: library part 1000512, "CAP CER 0.015UF 16V 10% X7R 0402", Manufacturer=Murata, Manufacturer_Part_Number=GRM155R71C153KA01D, Package_Type=0402, Temp_Coef=X7R, Tolerance=10%, Voltage=16V
C31 C34: library part 1000073, "CAP CER 1UF 6.3V 20% X5R 0402", Manufacturer=Murata, Manufacturer_Part_Number=GRM155R60J105ME19D, Package_Type=0402, Temp_Coef=X5R, Voltage=6.3V
C67 C94: library part 1001167, "CAP CER 1UF 10V 10% X5R 0402"
C68 C71 C95 C98 C137 C138: library part 1002646, "CAP CER 33PF 50V C0G/NP0 0402", Manufacturer=Murata, Manufacturer_Part_Number=GCM1555C1H330JA16D, Package_Type=0402, Tolerance=5%, Voltage=50
C80 C107: library part 1001883, "CAP CER 0.22UF 6.3V X7R 0402", Manufacturer="Taiyo Yuden", Manufacturer_Part_Number=JMK105B7224KV-F, Package_Type=0402, Tolerance=10%, Voltage=6.3V
C114 C116: library part 1001166, "CAP CER 22PF 50V 5% NP0 0402", Manufacturer=Murata, Manufacturer_Part_Number=GRM1555C1H220JA01D, Package_Type=0402, Temp_Coef="C0G, NP0", Tolerance=5%, Voltage=50V
C117: library part 1002727, "CAP CER 2200PF 50V X7R 5% 0603", Manufacturer=Kemet, Manufacturer_Part_Number=C0603C222J5RACTU, Package_Type=0603, Temp_Coef=X7R, Tolerance=5%, Voltage=50V
C161 C164 C165 C166 C168 C170: library part 1001541, "CAP CER 10PF 50V 5% NP0 0402", Manufacturer=Murata, Manufacturer_Part_Number=GRM1555C1H100JA01D, Package_Type=0402, Temp_Coef="C0G, NP0", Tolerance=5, Voltage=50V
C185: library part 1000566, "CAP CER 100UF 10V 20% X5R 1206", Manufacturer="TDK Corporation", Manufacturer_Part_Number=C3216X5R1A107M, Package_Type=1206, Temp_Coef=X5R, Tolerance=20%, Voltage=10V
C190: library part 1002042, "2.2µF ±10% 50V X7R Ceramic Capacitor -55°C ~ 125°C Surface Mount, MLCC 1210 (3225 Metric) 0.126\" L x 0.098\" W (3.20mm x 2.50mm)", Manufacturer=AVX, Manufacturer_Part_Number=12105C225KAT2A, Package_Type=1210, Temp_Coef=X7R, Tolerance=10%, Voltage=50V
C195 C196: library part 1000970, "CAP CER 2.2UF 6.3V 20% X5R 0402", Manufacturer="TDK Corporation", Manufacturer_Alt_1="Taiyo Yuden", Manufacturer_Alt_1_Part_Number=JMK105BJ225MV-F, Manufacturer_Part_Number=C1005X5R0J225M050BC, Package_Type=0402, Temp_Coef=X5R, Tolerance=20, Voltage=6.3V
D1 D3 D4 D7 D8 D9 D10 D11 D12 D13 D14 D19 D20 D24 D25 D26 D27 D28 D29 D30: library part 1001637, "TVS DIODE 3.3VWM SOD923", Manufacturer="On Semiconductor", Package_Type=SMT
D2: library part 1000794, "DIODE SCHOTTKY 30V 200MA SOT323", Manufacturer="Fairchild Semiconductor", Manufacturer Alt 1=none, Manufacturer Part Num=0082610201, Package_Type=SOT323, Part Number=SDS1920004
D5 D31 D32 D33 D34: library part 1001189, "LED GREEN 573NM 1208 SMD", Manufacturer=Dialight, Package_Type=SMT
D6 D17 D18: library part 1001188, "LED YELLOW 588NM 1208 SMD", Manufacturer=Dialight, Package_Type=SMT
D15: library part 1001169, "DIODE SCHOTTKY 30V 0.2A SOT23-3", Manufacturer="Fairchild Semiconductor", Package_Type=SMT
D16: library part 1002593, "TVS DIODE 5.5V 4V 10DFN", Manufacturer="Phillips NXP", Package_Type=SON
D21: library part 1000231, "DIODE SCHOTTKY 40V 1A SOD123", Manufacturer="Diodes, Inc.", Package_Type=SOD123
D22 D23: library part 1002861, "TVS DIODE 5VWM 11.6VC 1610", Manufacturer=STMicroelectronics, Package_Type=SMT
D35: library part 1002592, "DIODE SCHOTTKY 30V 30MA SMINI2", Manufacturer="Panasonic - ECG", Package_Type=SODFL
FIDUCIAL1 FIDUCIAL2 FIDUCIAL3 FIDUCIAL4 FIDUCIAL5 FIDUCIAL6: library part CAD0023, "40 Mil Round Fiducial", Package_Type=SMT
FIL1: library part 1002745, "FILTER LC(T) 22PF SMD", Manufacturer=Murata, Package_Type=1206
J1: library part 1001105, "DC Power Jack", Manufacturer="Bobbintron Electrical Corp", Package_Type=TH
J2: library part 1002003, "CONN HEADER VERT 2POS .100 TIN", Manufacturer="TE Connectivity", Package_Type=TH
J3 J5 J6 J7 J8 J9 J14 J16 J28 J34 J49: library part 1001128, "CONN HEADER 2POS .100\" SGL GOLD", Manufacturer=Samtec, Manufacturer_Part_Number=TSW-102-07-G-S, Package_Type=TH
J4: library part 1001136, "CONN HEADER 2POS 1.25MM VERT TIN", Manufacturer=Molex, Manufacturer_Part_Number=53047-0210, Package_Type=TH
J10 J24: library part 1000027, "RF Connectors U.FL RECEPTACLE SMT GLD M CONTACT", Manufacturer=Hirose, Package_Type=SMT
J11 J25: library part 1002720, "CONN SMA JACK R/A 50 OHM L15.1MM PCB TH", Manufacturer="Bobbintron Electrical Corp", Package_Type=TH
J12 J20 J21: library part 1000034, "CONN HEADER 10POS DUAL .05\" SMD", Manufacturer=Samtec, Package_Type=SMT
J13 J63: library part 1002675, "USB 3.1 SHIELDED I/O RECP TYPE C GEN2", Manufacturer=Molex, Manufacturer_Part_Number=201267-0005, Package_Type=SMT
J15 J17 J50: library part 1002860, "CONN HEADER VERT 4POS 2.54MM", Manufacturer=Samtec, Manufacturer_Part_Number=TSW-104-07-G-S, Package_Type=TH
J18: library part 1001137, "CONN HEADER 4POS 1.25MM VERT TIN", Manufacturer=Molex, Manufacturer_Part_Number=53047-0410, Package_Type=TH
J19: library part 1001130, "SMCONN,MINI PCI EXP, 6.8MM HT", Manufacturer=Foxconn, Manufacturer_Part_Number=AS0B226-S68Q-7H, Package_Type=SMT
J22: library part 1001120, "MEMORY CARD 6POS PUSH/PULL SMD", Manufacturer=Molex, Package_Type=SMT
J23: library part 1001118, "CONN TRANSFLSH R/A PUSH-PUSH SMD", Manufacturer=Molex, Package_Type=SMT
J26 J27: library part 1002612, "CONN MAGJACK 1PORT 1000 BASE-T IND", Manufacturer=XMultiple, Manufacturer_Part_Number=XMG-J1B2211NPA-1-DIG, Package_Type=TH
J29: library part 1001144, "CONN FPC 40POS 0.5MM PITCH SMD", Manufacturer=Omron, Manufacturer_Part_Number=XF2M-4015-1A, Package_Type=SMT
J30: library part 1001866, "CONN FFC FPC VERT 15POS 1MM SMD", Manufacturer=FCI, Package_Type=SMT
J31: library part 1001132, "CONN HEADER 20POS 1.25MM R/A SMD", Manufacturer=Hirose, Manufacturer_Part_Number=DF14A-20P-1.25H, Package_Type=SMT
J32: library part 1002870, "CONN HDMI 2.1 RA SMT 48GBPS", Manufacturer="Adam Tech"
J33: library part 1001121, "USB Stacked Dual A type", Manufacturer=KYCON, Package_Type=TH
J35 J36: library part 1002596, "CONN JACK STEREO 3.5MM R/A", Manufacturer="CUI Inc.", Package_Type=TH
J37 J38: library part 1001495, "CONN RCPT 2MM 10POS SMD", Manufacturer=Samtec, Package_Type=SMT
J39 J40: library part 1002848, "CONN HDR 8POS 0.1 GOLD PCB", Manufacturer=Sullins, Manufacturer_Part_Number=PPPC081LFBN-RC, Package_Type=TH
J41 J42: library part 1002751, "CONN HEADER VERT 20POS 2.54MM", Manufacturer=Samtec, Package_Type=TH
J43 J45 J51 J52 J53 J54 J55 J56 J57 J58 J59 J60 J61 J62 J64 J66: library part 1002832, "CONN HEADER 3POS .100\" SGL GOLD", Manufacturer=Samtec, Manufacturer_Part_Number=TSW-103-07-G-S, Package_Type=TH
